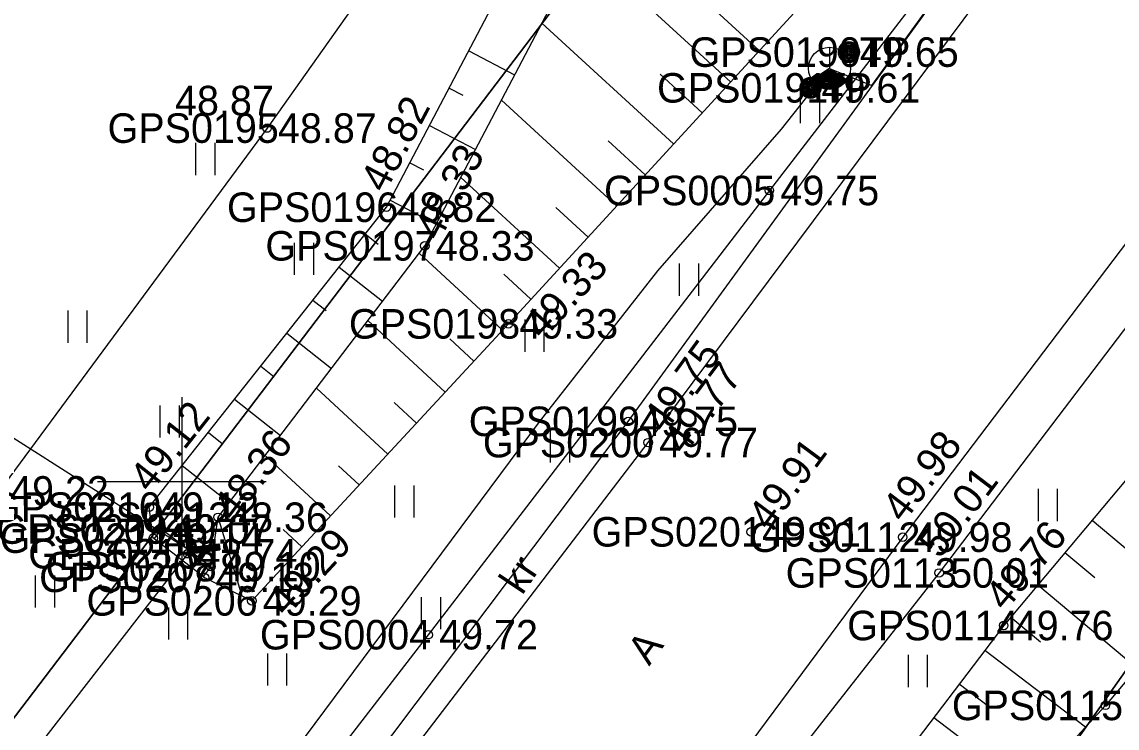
# Model space of a CAD drawing. Extents: x 563121 to 567545, y 6570841 to 6581299.
# Drawn here: x 565796.21 to 565822.17, y 6571844.15 to 6571860.9 of the extents above; entities that cross this region are included whole.
import ezdxf

# ---------------------------------------------------------------- set-up
doc = ezdxf.new("R2010")
doc.units = 0
for name, color, linetype in [('HALJASTUS', 7, 'Continuous'), ('KORGUS-EH2000', 7, 'Continuous'), ('MOOTKORG-EH2000', 7, 'Continuous'), ('MOOTMPUNKT', 7, 'Continuous'), ('MOOTNR', 7, 'Continuous'), ('MOOTPIIR', 7, 'Continuous'), ('PIIR', 7, 'Continuous'), ('POST', 7, 'Continuous'), ('RELJEEF', 7, 'Continuous'), ('SIKAEV', 7, 'Continuous'), ('SITRASS', 7, 'Continuous'), ('TEE', 7, 'Continuous'), ('TRUUP', 7, 'Continuous'), ('VORK', 7, 'Continuous')]:
    doc.layers.add(name, color=color, linetype=linetype)

msp = doc.modelspace()

# ---------------------------------------------------------------- linework, layer by layer
at = {"layer": 'HALJASTUS'}
for p, q in [((565814.662, 6571859.257), (565814.662, 6571858.496)), ((565815.117, 6571859.257), (565815.117, 6571858.496)), ((565800.327, 6571858.026), (565800.327, 6571857.265)), ((565800.783, 6571858.026), (565800.783, 6571857.265)), ((565802.664, 6571855.656), (565802.664, 6571854.895)), ((565803.119, 6571855.656), (565803.119, 6571854.895)), ((565811.794, 6571855.164), (565811.794, 6571854.403)), ((565812.249, 6571855.164), (565812.249, 6571854.403)), ((565797.297, 6571854.049), (565797.297, 6571853.288)), ((565797.752, 6571854.049), (565797.752, 6571853.288)), ((565808.132, 6571853.836), (565808.132, 6571853.075)), ((565808.587, 6571853.836), (565808.587, 6571853.075)), ((565799.48, 6571851.8), (565799.48, 6571851.039)), ((565799.935, 6571851.8), (565799.935, 6571851.039)), ((565808.734, 6571851.209), (565808.734, 6571850.448)), ((565809.189, 6571851.209), (565809.189, 6571850.448)), ((565805.047, 6571849.901), (565805.047, 6571849.14)), ((565805.502, 6571849.901), (565805.502, 6571849.14)), ((565820.301, 6571849.819), (565820.301, 6571849.058)), ((565820.756, 6571849.819), (565820.756, 6571849.058)), ((565796.526, 6571847.768), (565796.526, 6571847.007)), ((565796.981, 6571847.768), (565796.981, 6571847.007)), ((565805.675, 6571847.254), (565805.675, 6571846.493)), ((565806.13, 6571847.254), (565806.13, 6571846.493)), ((565799.682, 6571847.009), (565799.682, 6571846.248)), ((565800.137, 6571847.009), (565800.137, 6571846.248)), ((565802.029, 6571845.917), (565802.029, 6571845.156)), ((565802.484, 6571845.917), (565802.484, 6571845.156)), ((565817.218, 6571845.883), (565817.218, 6571845.122)), ((565817.673, 6571845.883), (565817.673, 6571845.122))]:
    msp.add_line(p, q, dxfattribs=at)
at = {"layer": 'KORGUS-EH2000'}
for centre in [(565802.021, 6571858.377), (565804.852, 6571856.501), (565805.762, 6571855.585), (565807.743, 6571853.735), (565810.584, 6571851.423), (565811.058, 6571850.919), (565799.23, 6571849.388), (565800.861, 6571849.149), (565813.497, 6571848.803), (565817.092, 6571848.675), (565817.957, 6571847.828), (565801.66, 6571847.165), (565819.486, 6571846.581), (565821.897, 6571844.686)]:
    msp.add_circle(centre, 0.1, dxfattribs=at)
at = {"layer": 'MOOTMPUNKT'}
for centre in [(565815.817, 6571860.18), (565814.907, 6571859.332), (565802.021, 6571858.377), (565813.931, 6571856.898), (565804.852, 6571856.501), (565805.762, 6571855.585), (565807.743, 6571853.735), (565810.584, 6571851.423), (565811.058, 6571850.919), (565799.23, 6571849.388), (565800.861, 6571849.149), (565799.323, 6571848.653), (565799.524, 6571848.869), (565813.497, 6571848.803), (565817.092, 6571848.675), (565800.139, 6571848.282), (565800.688, 6571847.978), (565800.538, 6571847.723), (565817.957, 6571847.828), (565801.66, 6571847.165), (565819.486, 6571846.581), (565805.842, 6571846.363), (565821.897, 6571844.686)]:
    msp.add_circle(centre, 0.1, dxfattribs=at)
at = {"layer": 'MOOTPIIR'}
msp.add_lwpolyline([(565823.283, 6571871.288), (565820.939, 6571873.864), (565815.364, 6571875.639), (565813.463, 6571874.16), (565808.89, 6571868.083), (565802.021, 6571858.377), (565795.67, 6571849.773), (565782.207, 6571833.008), (565776.308, 6571825.832), (565781.278, 6571820.922), (565782.262, 6571820.691), (565783.542, 6571819.443), (565784.347, 6571818.115), (565785.017, 6571817.401), (565789.374, 6571812.429), (565790.175, 6571811.534), (565801.221, 6571799.668)], dxfattribs=at)
at = {"layer": 'PIIR'}
for points in [[(566138.88, 6572289.1), (566071.95, 6572189.53), (566056.92, 6572168.48), (566043.44, 6572149.59), (566020.47, 6572117.41), (565845.87, 6571876.56), (565833.02, 6571860.66), (565803.59, 6571818.77), (565766.84, 6571778.8), (565712.27, 6571733.72), (565636.36, 6571689.97), (565561.65, 6571658.97), (565400, 6571600), (565315, 6571572), (565230, 6571552), (564980, 6571552), (564921.56, 6571543.26)], [(564959.63, 6571567.88), (565247.22, 6571575.87), (565310, 6571592), (565385.09, 6571617.94), (565603.34, 6571696.36), (565663.71, 6571724.88), (565720.01, 6571762.52), (565767.05, 6571806.3), (565831.51, 6571891.07), (565894.85, 6571978.6), (565929.68, 6572026.82), (566028.25, 6572163.26), (566043.71, 6572184.75), (566068.58, 6572219.3), (566114.67, 6572283.35)]]:
    msp.add_lwpolyline(points, dxfattribs=at)
for points in [[(565385.09, 6571617.94), (565348.3, 6571706.93), (565808.88, 6572174.3), (565817.95, 6572187.54), (565914.67, 6572223.63), (565927.34, 6572201.79), (566013.66, 6572213.36), (566028.25, 6572163.26), (565929.68, 6572026.82), (565869.35, 6572071.5), (565833.75, 6572019.48), (565773.79, 6571931.89), (565831.51, 6571891.07), (565767.05, 6571806.3), (565720.01, 6571762.52), (565663.71, 6571724.88), (565603.34, 6571696.36)], [(565833.02, 6571860.66), (565851.06, 6571859.65), (565901.01, 6571846.54), (565960.44, 6571833.78), (565973.49, 6571828.72), (566023.53, 6571796.39), (566089.86, 6571753.57), (566110.96, 6571742.32), (566147.53, 6571725.81), (566160.83, 6571717.7), (565835.49, 6571610.61), (565803.59, 6571818.77)]]:
    msp.add_lwpolyline(points, close=True, dxfattribs=at)
at = {"layer": 'POST'}
for centre, radius in [((565815.817, 6571860.18), 0.25), ((565815.817, 6571860.18), 0.225), ((565815.817, 6571860.18), 0.2), ((565815.817, 6571860.18), 0.175), ((565815.817, 6571860.18), 0.15), ((565815.817, 6571860.18), 0.125), ((565815.817, 6571860.18), 0.1), ((565815.817, 6571860.18), 0.075), ((565815.817, 6571860.18), 0.05), ((565815.817, 6571860.18), 0.025), ((565814.907, 6571859.332), 0.25), ((565814.907, 6571859.332), 0.225), ((565814.907, 6571859.332), 0.2), ((565814.907, 6571859.332), 0.175), ((565814.907, 6571859.332), 0.15), ((565814.907, 6571859.332), 0.125), ((565814.907, 6571859.332), 0.1), ((565814.907, 6571859.332), 0.075), ((565814.907, 6571859.332), 0.05), ((565814.907, 6571859.332), 0.025)]:
    msp.add_circle(centre, radius, dxfattribs=at)
at = {"layer": 'RELJEEF'}
for p, q in [((565813.011, 6571859.477), (565809.5, 6571862.699)), ((565813.687, 6571860.214), (565812.575, 6571861.234)), ((565811.659, 6571858.003), (565808.538, 6571860.867)), ((565806.804, 6571860.212), (565807.892, 6571859.639)), ((565812.335, 6571858.74), (565811.34, 6571859.653)), ((565806.338, 6571859.327), (565806.665, 6571859.155)), ((565810.307, 6571856.53), (565807.576, 6571859.036)), ((565805.873, 6571858.442), (565806.962, 6571857.868)), ((565810.983, 6571857.267), (565810.105, 6571858.072)), ((565805.407, 6571857.557), (565805.734, 6571857.385)), ((565808.955, 6571855.056), (565806.613, 6571857.204)), ((565804.942, 6571856.671), (565806.032, 6571856.098)), ((565809.631, 6571855.793), (565808.87, 6571856.491)), ((565804.351, 6571855.868), (565804.656, 6571855.627)), ((565807.602, 6571853.583), (565805.629, 6571855.41)), ((565803.731, 6571855.083), (565804.761, 6571854.269)), ((565808.279, 6571854.319), (565807.635, 6571854.91)), ((565803.111, 6571854.298), (565803.424, 6571854.051)), ((565806.243, 6571852.115), (565804.412, 6571853.811)), ((565802.491, 6571853.514), (565803.549, 6571852.678)), ((565806.923, 6571852.849), (565806.352, 6571853.378)), ((565801.871, 6571852.729), (565802.193, 6571852.475)), ((565804.885, 6571850.648), (565803.194, 6571852.213)), ((565801.251, 6571851.945), (565802.337, 6571851.087)), ((565805.564, 6571851.382), (565805.036, 6571851.871)), ((565800.631, 6571851.16), (565800.961, 6571850.9)), ((565803.526, 6571849.18), (565801.977, 6571850.614)), ((565800.011, 6571850.376), (565801.125, 6571849.495)), ((565804.205, 6571849.914), (565803.719, 6571850.364)), ((565800.688, 6571847.978), (565800.861, 6571849.149)), ((565801.433, 6571847.277), (565800.861, 6571849.149)), ((565821.582, 6571849.079), (565823.933, 6571847.107)), ((565802.847, 6571848.446), (565802.403, 6571848.857)), ((565820.939, 6571848.313), (565821.644, 6571847.722)), ((565820.296, 6571847.547), (565822.646, 6571845.576)), ((565819.654, 6571846.781), (565820.358, 6571846.19)), ((565819.039, 6571845.993), (565821.427, 6571844.177)), ((565818.434, 6571845.197), (565819.127, 6571844.669)), ((565817.828, 6571844.401), (565820.064, 6571842.701))]:
    msp.add_line(p, q, dxfattribs=at)
for points in [[(565800.51, 6571847.744), (565800.538, 6571847.723), (565801.66, 6571847.165), (565807.743, 6571853.735), (565820.396, 6571867.526), (565823.283, 6571871.288)], [(565800.861, 6571849.149), (565805.762, 6571855.585), (565812.288, 6571868.004), (565812.929, 6571869.63)], [(565799.345, 6571848.635), (565799.323, 6571848.653), (565799.23, 6571849.388), (565804.852, 6571856.501), (565810.46, 6571867.163), (565812.288, 6571868.004)], [(565844.04, 6571859.801), (565839.307, 6571861.411), (565835.818, 6571862.396), (565833.848, 6571861.926), (565831.495, 6571861.254), (565830.033, 6571859.153), (565819.486, 6571846.581), (565806.328, 6571829.271), (565803.644, 6571823.76)], [(565830.061, 6571854.393), (565821.897, 6571844.686), (565807.174, 6571828.74), (565803.644, 6571823.76)]]:
    msp.add_lwpolyline(points, dxfattribs=at)
at = {"layer": 'SIKAEV'}
for p, q in [((565815.357, 6571860.294), (565815.357, 6571859.794)), ((565815.357, 6571859.794), (565814.942, 6571859.519)), ((565815.357, 6571859.794), (565815.772, 6571859.519))]:
    msp.add_line(p, q, dxfattribs=at)
msp.add_circle((565815.357, 6571859.794), 0.5, dxfattribs=at)
for radius in [0.275, 0.25, 0.225, 0.2, 0.175, 0.15, 0.125, 0.1, 0.075, 0.05, 0.475, 0.45, 0.425, 0.4, 0.375, 0.35, 0.325, 0.3]:
    msp.add_arc((565815.357, 6571859.794), radius, 213.5305, 326.4695, dxfattribs=at)
at = {"layer": 'SITRASS'}
for points in [[(565827.937, 6571875.522), (565819.589, 6571864.258), (565813.931, 6571856.898), (565805.842, 6571846.363), (565798.797, 6571837.231), (565791.619, 6571827.726), (565784.171, 6571818.664)], [(565783.542, 6571819.443), (565787.788, 6571824.729), (565795.262, 6571834.475), (565801.765, 6571842.375), (565808.482, 6571851.414), (565811.284, 6571854.993), (565814.22, 6571858.353), (565815.357, 6571859.794), (565816.36, 6571859.39), (565822.04, 6571867.24), (565823.485, 6571869.196), (565824.591, 6571870.729)]]:
    msp.add_lwpolyline(points, dxfattribs=at)
at = {"layer": 'TEE'}
for points in [[(565784.347, 6571818.115), (565798.874, 6571835.854), (565810.584, 6571851.423), (565821.499, 6571866.441), (565824.465, 6571870.379)], [(565785.017, 6571817.401), (565799.254, 6571835.472), (565811.058, 6571850.919), (565822.074, 6571865.705), (565825.255, 6571869.896)], [(565839.194, 6571863.521), (565833.439, 6571863.766), (565828.407, 6571862.073), (565825.907, 6571860.285), (565817.092, 6571848.675), (565804.137, 6571831.188), (565797.898, 6571823.166), (565798.048, 6571821.994), (565800.139, 6571818.615), (565801.078, 6571813.504), (565797.777, 6571812.08), (565794.654, 6571813.34), (565791.141, 6571814.563), (565789.374, 6571812.429)], [(565833.439, 6571863.766), (565828.71, 6571861.712), (565827.373, 6571860.217), (565817.957, 6571847.828), (565804.535, 6571830.717), (565801.583, 6571826.805), (565800.955, 6571825.15), (565801.025, 6571821.866), (565801.467, 6571818.976), (565802.633, 6571814.638), (565802.718, 6571813.36), (565804.674, 6571805.685), (565807.231, 6571788.975), (565811.315, 6571764.792), (565815.474, 6571739.551), (565820.53, 6571709.209), (565821.038, 6571705.752), (565823.803, 6571687.466)]]:
    msp.add_lwpolyline(points, dxfattribs=at)
at = {"layer": 'TRUUP'}
for p, q in [((565800.176, 6571849.066), (565800.035, 6571849.048)), ((565800.035, 6571849.048), (565800.133, 6571848.276)), ((565800.064, 6571849.051), (565800.042, 6571848.99)), ((565800.092, 6571849.055), (565800.049, 6571848.935)), ((565800.12, 6571849.058), (565800.056, 6571848.88)), ((565800.148, 6571849.062), (565800.063, 6571848.825)), ((565800.175, 6571849.066), (565800.071, 6571848.769)), ((565800.183, 6571849.013), (565800.078, 6571848.714)), ((565800.106, 6571849.057), (565800.195, 6571848.355)), ((565800.176, 6571849.066), (565800.257, 6571848.435)), ((565800.19, 6571848.957), (565800.085, 6571848.659)), ((565800.197, 6571848.902), (565800.092, 6571848.604)), ((565800.204, 6571848.847), (565800.099, 6571848.549)), ((565800.211, 6571848.792), (565800.106, 6571848.494)), ((565800.218, 6571848.737), (565800.113, 6571848.439)), ((565800.225, 6571848.682), (565800.12, 6571848.384)), ((565800.232, 6571848.627), (565800.127, 6571848.329)), ((565800.239, 6571848.572), (565800.135, 6571848.276)), ((565800.246, 6571848.517), (565800.162, 6571848.279)), ((565800.257, 6571848.435), (565800.887, 6571848.515)), ((565800.521, 6571848.469), (565800.468, 6571848.318)), ((565800.549, 6571848.472), (565800.496, 6571848.322)), ((565800.576, 6571848.476), (565800.523, 6571848.325)), ((565800.604, 6571848.479), (565800.551, 6571848.329)), ((565800.632, 6571848.483), (565800.579, 6571848.332)), ((565800.66, 6571848.486), (565800.607, 6571848.336)), ((565800.688, 6571848.49), (565800.634, 6571848.339)), ((565800.715, 6571848.493), (565800.662, 6571848.343)), ((565800.743, 6571848.497), (565800.69, 6571848.347)), ((565800.771, 6571848.5), (565800.718, 6571848.35)), ((565800.799, 6571848.504), (565800.745, 6571848.354)), ((565800.826, 6571848.507), (565800.773, 6571848.357)), ((565800.854, 6571848.511), (565800.801, 6571848.361)), ((565800.882, 6571848.514), (565800.829, 6571848.364)), ((565800.893, 6571848.471), (565800.857, 6571848.368)), ((565800.887, 6571848.515), (565800.905, 6571848.374)), ((565795.106, 6571841.78), (565800.195, 6571848.355)), ((565800.133, 6571848.276), (565800.905, 6571848.374)), ((565800.253, 6571848.461), (565800.19, 6571848.283)), ((565800.195, 6571848.355), (565800.896, 6571848.445)), ((565800.271, 6571848.437), (565800.218, 6571848.286)), ((565800.299, 6571848.44), (565800.246, 6571848.29)), ((565800.327, 6571848.444), (565800.273, 6571848.293)), ((565800.354, 6571848.447), (565800.301, 6571848.297)), ((565800.382, 6571848.451), (565800.329, 6571848.301)), ((565800.41, 6571848.454), (565800.357, 6571848.304)), ((565800.438, 6571848.458), (565800.384, 6571848.308)), ((565800.465, 6571848.461), (565800.412, 6571848.311)), ((565800.493, 6571848.465), (565800.44, 6571848.315)), ((565800.9, 6571848.416), (565800.884, 6571848.371))]:
    msp.add_line(p, q, dxfattribs=at)
msp.add_lwpolyline([(565800.195, 6571848.355), (565793.374, 6571852.7), (565787.316, 6571852.7)], dxfattribs=at)
msp.add_lwpolyline([(565799.524, 6571848.869), (565800.688, 6571847.978), (565800.51, 6571847.744), (565799.345, 6571848.635)], close=True, dxfattribs=at)
at = {"layer": 'VORK'}
for p, q in [((565800, 6571852), (565800, 6571848)), ((565798, 6571850), (565802, 6571850))]:
    msp.add_line(p, q, dxfattribs=at)

# ---------------------------------------------------------------- texts
at = {"layer": 'KORGUS-EH2000'}
msp.add_text(' 48.87', height=0.7, dxfattribs=at).set_placement((565799.58, 6571858.68))
for s, rotation, p in [(' 48.82', 62.2559, (565804.697, 6571856.582)), (' 48.33', 62.2822, (565805.982, 6571855.441)), (' 49.33', 47.4647, (565808.387, 6571853.143)), (' 49.75', 53.9909, (565811.292, 6571850.908)), (' 49.77', 53.3125, (565811.759, 6571850.396)), (' 49.12', 51.6776, (565799.093, 6571849.497)), (' 48.36', 52.7081, (565801.085, 6571848.813)), (' 49.98', 52.7893, (565816.952, 6571848.781)), (' 49.91', 53.4535, (565813.778, 6571848.595)), (' 50.01', 52.7636, (565817.817, 6571847.934)), (' 49.76', 50.0048, (565819.352, 6571846.694)), (' 49.29', 47.2055, (565802.302, 6571846.57))]:
    msp.add_text(s, height=0.7, rotation=rotation, dxfattribs=at).set_placement(p)
at = {"layer": 'MOOTKORG-EH2000'}
for s, p in [(' 49.65', (565815.817, 6571859.83)), (' 49.61', (565814.907, 6571858.982)), (' 48.87', (565802.021, 6571858.027)), (' 49.75', (565813.931, 6571856.548)), (' 48.82', (565804.852, 6571856.151)), (' 48.33', (565805.762, 6571855.235)), (' 49.33', (565807.743, 6571853.385)), (' 49.75', (565810.584, 6571851.073)), (' 49.77', (565811.058, 6571850.569)), (' 49.22', (565795.67, 6571849.423)), (' 49.12', (565799.23, 6571849.038)), (' 48.36', (565800.861, 6571848.799)), (' 49.14', (565799.323, 6571848.303)), (' 49.07', (565799.524, 6571848.519)), (' 49.91', (565813.497, 6571848.453)), (' 49.98', (565817.092, 6571848.325)), (' 48.74', (565800.139, 6571847.933)), (' 49.10', (565800.688, 6571847.628)), (' 49.13', (565800.538, 6571847.373)), (' 50.01', (565817.957, 6571847.478)), (' 49.29', (565801.66, 6571846.815)), (' 49.76', (565819.486, 6571846.231)), (' 49.72', (565805.842, 6571846.013))]:
    msp.add_text(s, height=0.7, dxfattribs=at).set_placement(p)
at = {"layer": 'MOOTNR'}
for s, p in [('GPS0190 ', (565812.037, 6571859.83)), ('GPS0191 ', (565811.268, 6571858.982)), ('GPS0195 ', (565798.241, 6571858.027)), ('GPS0005 ', (565810.011, 6571856.548)), ('GPS0196 ', (565801.072, 6571856.151)), ('GPS0197 ', (565801.982, 6571855.235)), ('GPS0198 ', (565803.963, 6571853.385)), ('GPS0199 ', (565806.804, 6571851.073)), ('GPS0200 ', (565807.138, 6571850.569)), ('GPS0210 ', (565795.451, 6571849.038)), ('GPS0212 ', (565797.081, 6571848.799)), ('GPS0209 ', (565795.604, 6571848.519)), ('GPS0211 ', (565795.683, 6571848.303)), ('GPS0201 ', (565809.717, 6571848.453)), ('GPS0112 ', (565813.452, 6571848.325)), ('GPS0213 ', (565796.359, 6571847.933)), ('GPS0208 ', (565796.769, 6571847.628)), ('GPS0207 ', (565796.618, 6571847.373)), ('GPS0113 ', (565814.317, 6571847.478)), ('GPS0206 ', (565797.74, 6571846.815)), ('GPS0114 ', (565815.776, 6571846.231)), ('GPS0004 ', (565801.852, 6571846.013)), ('GPS0115 ', (565818.257, 6571844.336))]:
    msp.add_text(s, height=0.7, dxfattribs=at).set_placement(p)
at = {"layer": 'POST'}
for p in [(565815.817, 6571859.83), (565814.907, 6571858.982)]:
    msp.add_text(' TP', height=0.7, dxfattribs=at).set_placement(p)
at = {"layer": 'TEE'}
for s, rotation, p in [('kr', 56.1256, (565808.069, 6571847.279)), ('A', 53.7346, (565811.08, 6571845.606))]:
    msp.add_text(s, height=0.7, rotation=rotation, dxfattribs=at).set_placement(p)

doc.saveas('drawing.dxf')
